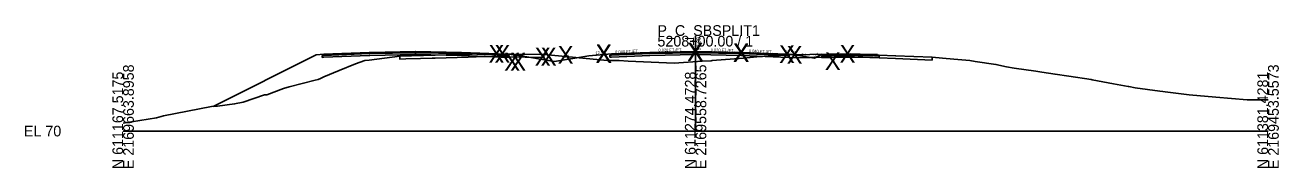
# Model space of a CAD drawing. Extents: x -26 to 1303, y -3010 to 12023.
# Drawn here: x 974.3 to 1302.8, y 5990.3 to 6027.8 of the extents above; entities that cross this region are included whole.
import ezdxf

# ---------------------------------------------------------------- set-up
doc = ezdxf.new("R2010")
doc.units = 0
for name, color, linetype in [('RD_GPK_XS_Cell', 7, 'Continuous'), ('RD_GPK_XS_Text_Node', 7, 'Continuous'), ('RD_XS_Base', 7, 'Continuous'), ('RD_XS_ExGround', 7, 'Continuous'), ('RD_XS_ExPaveRet', 7, 'Continuous'), ('RD_XS_Greenside', 7, 'Continuous'), ('RD_XS_Pave', 7, 'Continuous'), ('RD_XS_PaveOvlay_CP', 7, 'Continuous'), ('RD_XS_TieSlope', 7, 'Continuous'), ('RD_XS_TX_Elev_EX', 7, 'Continuous'), ('RD_XS_TX_Elev_PR', 7, 'Continuous'), ('RD_XS_TX_ShdSlope', 7, 'Continuous'), ('RD_XS_TX_Slope', 7, 'Continuous')]:
    doc.layers.add(name, color=color, linetype=linetype)

msp = doc.modelspace()

# ---------------------------------------------------------------- linework, layer by layer
at = {"layer": 'RD_GPK_XS_Cell'}
for p, q in [((1150, 6000), (1150, 6025)), ((1000, 6000), (1150, 6000)), ((1150, 6000), (1300, 6000))]:
    msp.add_line(p, q, dxfattribs=at)
at = {"layer": 'RD_XS_Base'}
for p, q in [((1052.12, 6019.84), (1052.61, 6019.86)), ((1052.12, 6019.83), (1052.12, 6019.84)), ((1052.12, 6019.34), (1052.12, 6019.83)), ((1052.61, 6019.36), (1052.12, 6019.34)), ((1052.61, 6019.86), (1052.62, 6019.86)), ((1052.62, 6019.36), (1052.61, 6019.36)), ((1052.62, 6019.86), (1064.47, 6020.33)), ((1064.47, 6019.83), (1052.62, 6019.36)), ((1064.47, 6020.33), (1064.62, 6020.34)), ((1064.62, 6019.84), (1064.47, 6019.83)), ((1064.62, 6020.34), (1076.6, 6020.58)), ((1076.6, 6020.08), (1064.62, 6019.84)), ((1076.6, 6020.58), (1076.62, 6020.58)), ((1076.62, 6020.08), (1076.6, 6020.08)), ((1076.62, 6020.58), (1076.62, 6020.74)), ((1076.62, 6020.74), (1076.62, 6020.74)), ((1076.62, 6020.74), (1076.62, 6020.74)), ((1076.62, 6020.74), (1076.62, 6020.08)), ((1076.62, 6020.58), (1076.62, 6020.74)), ((1076.62, 6020.74), (1076.62, 6020.08)), ((1076.62, 6020.58), (1076.62, 6020.58)), ((1076.62, 6020.58), (1076.62, 6020.08)), ((1076.65, 6020.58), (1076.62, 6020.58)), ((1076.62, 6020.58), (1076.62, 6020.08)), ((1088.62, 6020.34), (1076.62, 6020.58)), ((1076.62, 6020.58), (1076.62, 6020.58)), ((1076.62, 6020.08), (1076.65, 6020.08)), ((1076.62, 6020.08), (1076.62, 6020.08)), ((1076.62, 6020.08), (1076.62, 6020.08)), ((1076.62, 6020.08), (1088.62, 6019.84)), ((1100.62, 6019.86), (1088.62, 6020.34)), ((1088.62, 6019.84), (1101.12, 6019.34)), ((1090.62, 6020.26), (1090.62, 6020.26)), ((1090.62, 6019.76), (1090.62, 6019.76)), ((1101.12, 6019.84), (1100.62, 6019.86)), ((1100.62, 6019.86), (1100.62, 6019.86)), ((1101.12, 6019.34), (1101.12, 6019.84)), ((1101.12, 6019.84), (1101.12, 6019.84)), ((1101.12, 6019.34), (1101.12, 6019.34)), ((1101.12, 6019.34), (1101.12, 6019.34)), ((1127.5, 6019.92), (1128, 6019.94)), ((1127.5, 6019.42), (1127.5, 6019.92)), ((1127.5, 6019.92), (1127.5, 6019.92)), ((1128, 6019.44), (1127.5, 6019.42)), ((1127.5, 6019.42), (1127.5, 6019.42)), ((1127.5, 6019.42), (1127.5, 6019.42)), ((1128, 6019.94), (1138, 6020.34)), ((1128, 6019.94), (1128, 6019.94)), ((1138, 6019.84), (1128, 6019.44)), ((1128, 6019.44), (1128, 6019.44)), ((1136, 6020.26), (1136, 6020.26)), ((1136, 6019.76), (1136, 6019.76)), ((1138, 6020.34), (1150, 6020.58)), ((1150, 6020.08), (1138, 6019.84)), ((1150, 6020.58), (1150, 6020.74)), ((1150, 6020.74), (1150, 6020.08)), ((1150, 6020.58), (1150, 6020.08)), ((1150, 6020.58), (1150, 6020.58)), ((1162, 6020.34), (1150, 6020.58)), ((1150, 6020.58), (1150, 6020.58)), ((1150, 6020.08), (1150, 6020.08)), ((1150, 6020.08), (1150, 6020.08)), ((1150, 6020.08), (1162, 6019.84)), ((1173.93, 6019.86), (1162, 6020.34)), ((1162, 6020.34), (1162, 6020.34)), ((1162, 6019.84), (1162, 6019.84)), ((1162, 6019.84), (1174.43, 6019.34)), ((1174.43, 6019.84), (1173.93, 6019.86)), ((1173.93, 6019.86), (1173.93, 6019.86)), ((1174.43, 6019.34), (1174.43, 6019.84)), ((1174.43, 6019.84), (1174.43, 6019.84)), ((1174.43, 6019.34), (1174.43, 6019.34)), ((1174.43, 6019.34), (1174.43, 6019.34)), ((1183.11, 6019.77), (1183.61, 6019.78)), ((1183.11, 6019.27), (1183.11, 6019.77)), ((1183.61, 6019.28), (1183.11, 6019.27)), ((1183.61, 6019.78), (1185.61, 6019.82)), ((1185.61, 6019.32), (1183.61, 6019.28)), ((1185.61, 6019.82), (1190.61, 6019.92)), ((1190.61, 6019.42), (1185.61, 6019.32)), ((1190.61, 6019.98), (1190.61, 6020.08)), ((1190.61, 6020.08), (1190.61, 6019.82)), ((1190.61, 6019.92), (1190.61, 6019.98)), ((1192.56, 6019.88), (1190.61, 6019.92)), ((1190.61, 6019.92), (1190.61, 6019.42)), ((1190.61, 6019.82), (1190.61, 6019.42)), ((1190.61, 6019.42), (1192.56, 6019.38)), ((1195.62, 6019.82), (1192.56, 6019.88)), ((1192.56, 6019.38), (1195.62, 6019.32)), ((1196.87, 6019.79), (1195.62, 6019.82)), ((1195.62, 6019.32), (1196.56, 6019.3)), ((1196.56, 6019.3), (1198.12, 6019.27)), ((1197.62, 6019.78), (1196.87, 6019.79)), ((1197.8, 6019.77), (1197.62, 6019.78)), ((1198.12, 6019.77), (1197.8, 6019.77)), ((1198.12, 6019.45), (1198.12, 6019.77)), ((1198.12, 6019.27), (1198.12, 6019.45))]:
    msp.add_line(p, q, dxfattribs=at)
at = {"layer": 'RD_XS_ExGround'}
msp.add_lwpolyline([(1000, 6002.05), (1008.76, 6003.47), (1010.61, 6003.99), (1023.16, 6006.48), (1024.75, 6006.52), (1029.19, 6007.11), (1031.43, 6007.56), (1034.26, 6008.56), (1037.02, 6009.51), (1037.62, 6009.51), (1042.06, 6011.15), (1043.48, 6011.61), (1050.29, 6013.32), (1051.09, 6013.52), (1051.71, 6013.76), (1052.57, 6014.26), (1056.63, 6015.9), (1060.85, 6017.65), (1062.12, 6018.06), (1063.37, 6018.49), (1064.43, 6018.64), (1072.46, 6019.66), (1081.72, 6019.93), (1094.66, 6020.31), (1110.16, 6020.09), (1110.21, 6020.09), (1110.26, 6020.09), (1110.42, 6020.07), (1126.8, 6018.57), (1129.12, 6018.5), (1129.97, 6018.5), (1132.31, 6018.38), (1144.37, 6017.87), (1151.74, 6018.35), (1154.09, 6018.46), (1154.32, 6018.49), (1162.53, 6019.13), (1166.07, 6019.51), (1173.35, 6019.94), (1174.49, 6019.99), (1179.96, 6020.1), (1189.56, 6020.3), (1202.39, 6019.77), (1211.98, 6019.38), (1214.65, 6019.12), (1217.69, 6018.87), (1221.81, 6018.5), (1223.27, 6018.29), (1228.69, 6017.5), (1231.5, 6016.88), (1233.46, 6016.52), (1239.13, 6015.73), (1240.7, 6015.5), (1244.19, 6014.91), (1247.8, 6014.4), (1253.63, 6013.5), (1253.89, 6013.49), (1259.47, 6012.42), (1263.37, 6011.73), (1263.48, 6011.7), (1265.19, 6011.38), (1271.64, 6010.5), (1272.38, 6010.4), (1273.06, 6010.33), (1279.31, 6009.49), (1286.35, 6008.91), (1294.5, 6008.17), (1300, 6008.18)], dxfattribs=at)
at = {"layer": 'RD_XS_ExPaveRet'}
for points in [[(1074.06, 6019.71), (1072.46, 6019.66), (1072.46, 6019.1), (1072.46, 6018.91), (1074.06, 6018.96), (1077.91, 6019.07), (1080.94, 6019.16), (1081.72, 6019.18), (1090.37, 6019.43), (1094.66, 6019.56), (1100.53, 6019.48), (1110.16, 6019.34), (1110.21, 6019.34), (1110.21, 6019.34), (1110.21, 6019.34), (1110.21, 6019.34), (1110.21, 6019.34), (1110.21, 6020), (1110.21, 6020.09), (1110.21, 6020.09), (1110.21, 6020.09), (1110.21, 6020.09), (1110.21, 6020.09), (1110.16, 6020.09), (1100.53, 6020.23), (1094.66, 6020.31), (1090.37, 6020.18), (1081.72, 6019.93), (1080.94, 6019.91), (1077.91, 6019.82), (1074.06, 6019.71)], [(1074.06, 6019.71), (1072.46, 6019.66), (1072.46, 6019.1), (1072.46, 6018.91), (1074.06, 6018.96), (1077.91, 6019.07), (1080.94, 6019.16), (1081.72, 6019.18), (1090.37, 6019.43), (1094.66, 6019.56), (1100.53, 6019.48), (1110.16, 6019.34), (1110.21, 6019.34), (1110.21, 6019.34), (1110.21, 6019.34), (1110.21, 6019.34), (1110.21, 6020), (1110.21, 6020.09), (1110.21, 6020.09), (1110.21, 6020.09), (1110.21, 6020.09), (1110.16, 6020.09), (1100.53, 6020.23), (1094.66, 6020.31), (1090.37, 6020.18), (1081.72, 6019.93), (1080.94, 6019.91), (1077.91, 6019.82), (1074.06, 6019.71)], [(1211.98, 6019.38), (1202.39, 6019.77), (1202.39, 6019.77), (1189.56, 6020.3), (1189.56, 6020.3), (1179.96, 6020.1), (1179.96, 6020.1), (1174.49, 6019.99), (1174.49, 6019.99), (1174.49, 6019.24), (1174.49, 6019.24), (1174.49, 6019.24), (1179.96, 6019.35), (1179.96, 6019.35), (1189.56, 6019.55), (1189.56, 6019.55), (1202.39, 6019.02), (1202.39, 6019.02), (1211.98, 6018.63), (1211.98, 6018.63), (1211.98, 6018.63), (1211.98, 6019.38), (1211.98, 6019.38)], [(1211.98, 6019.38), (1202.39, 6019.77), (1189.56, 6020.3), (1179.96, 6020.1), (1174.49, 6019.99), (1174.49, 6019.99), (1174.49, 6019.24), (1174.49, 6019.24), (1179.96, 6019.35), (1189.56, 6019.55), (1202.39, 6019.02), (1211.98, 6018.63), (1211.98, 6019.38)]]:
    msp.add_lwpolyline(points, dxfattribs=at)
at = {"layer": 'RD_XS_Greenside'}
for p, q in [((1050.62, 6020.02), (1023.55, 6006.49)), ((1102.62, 6020.02), (1113.03, 6018.28)), ((1122, 6019.78), (1113.03, 6018.28)), ((1175.93, 6020.02), (1181.13, 6019.15)), ((1181.13, 6019.15), (1183.16, 6020.17))]:
    msp.add_line(p, q, dxfattribs=at)
at = {"layer": 'RD_XS_Pave'}
for p, q in [((1064.47, 6020.65), (1052.62, 6020.18)), ((1064.47, 6020.49), (1052.62, 6020.02)), ((1052.62, 6020.02), (1064.47, 6020.49)), ((1052.62, 6019.86), (1064.47, 6020.33)), ((1052.62, 6020.18), (1052.62, 6020.17)), ((1052.62, 6020.17), (1052.62, 6020.02)), ((1052.62, 6020.02), (1052.62, 6020.02)), ((1052.62, 6020.02), (1052.62, 6019.86)), ((1064.62, 6020.66), (1064.47, 6020.65)), ((1064.62, 6020.5), (1064.47, 6020.49)), ((1064.47, 6020.49), (1064.62, 6020.5)), ((1064.47, 6020.33), (1064.62, 6020.34)), ((1076.6, 6020.9), (1064.62, 6020.66)), ((1076.6, 6020.74), (1064.62, 6020.5)), ((1064.62, 6020.5), (1076.6, 6020.74)), ((1064.62, 6020.34), (1076.6, 6020.58)), ((1076.62, 6020.9), (1076.6, 6020.9)), ((1076.62, 6020.74), (1076.6, 6020.74)), ((1076.6, 6020.74), (1076.62, 6020.74)), ((1076.6, 6020.58), (1076.62, 6020.58)), ((1076.65, 6020.9), (1076.62, 6020.9)), ((1088.62, 6020.66), (1076.62, 6020.9)), ((1076.62, 6020.58), (1076.62, 6020.74)), ((1076.62, 6020.74), (1076.62, 6020.74)), ((1076.62, 6020.74), (1076.65, 6020.74)), ((1076.65, 6020.74), (1076.62, 6020.74)), ((1076.62, 6020.74), (1076.62, 6020.74)), ((1076.62, 6020.74), (1076.62, 6020.58)), ((1076.62, 6020.58), (1076.62, 6020.74)), ((1076.62, 6020.74), (1088.62, 6020.5)), ((1088.62, 6020.5), (1076.62, 6020.74)), ((1076.62, 6020.74), (1076.62, 6020.58)), ((1076.62, 6020.58), (1076.65, 6020.58)), ((1076.62, 6020.58), (1076.62, 6020.58)), ((1076.62, 6020.58), (1076.62, 6020.58)), ((1076.62, 6020.58), (1088.62, 6020.34)), ((1100.62, 6020.18), (1088.62, 6020.66)), ((1088.62, 6020.5), (1100.62, 6020.02)), ((1100.62, 6020.02), (1088.62, 6020.5)), ((1088.62, 6020.34), (1100.62, 6019.86)), ((1090.62, 6020.58), (1090.62, 6020.58)), ((1090.62, 6020.42), (1090.62, 6020.42)), ((1090.62, 6020.42), (1090.62, 6020.42)), ((1090.62, 6020.26), (1090.62, 6020.26)), ((1100.62, 6020.02), (1100.62, 6020.18)), ((1100.62, 6020.18), (1100.62, 6020.18)), ((1100.62, 6020.02), (1100.62, 6020.02)), ((1100.62, 6020.02), (1100.62, 6020.02)), ((1100.62, 6019.86), (1100.62, 6020.02)), ((1100.62, 6020.02), (1100.62, 6020.02)), ((1100.62, 6019.86), (1100.62, 6019.86)), ((1100.62, 6019.86), (1100.62, 6019.86)), ((1138, 6020.66), (1128, 6020.26)), ((1138, 6020.5), (1128, 6020.1)), ((1128, 6020.1), (1138, 6020.5)), ((1128, 6019.94), (1138, 6020.34)), ((1128, 6020.26), (1128, 6020.26)), ((1128, 6020.26), (1128, 6020.1)), ((1128, 6020.1), (1128, 6020.1)), ((1128, 6020.1), (1128, 6019.94)), ((1128, 6020.1), (1128, 6020.1)), ((1128, 6020.1), (1128, 6020.1)), ((1128, 6019.94), (1128, 6019.94)), ((1128, 6019.94), (1128, 6019.94)), ((1136, 6020.58), (1136, 6020.58)), ((1136, 6020.42), (1136, 6020.42)), ((1136, 6020.42), (1136, 6020.42)), ((1136, 6020.26), (1136, 6020.26)), ((1150, 6020.9), (1138, 6020.66)), ((1150, 6020.74), (1138, 6020.5)), ((1138, 6020.5), (1150, 6020.74)), ((1138, 6020.34), (1150, 6020.58)), ((1162, 6020.66), (1150, 6020.9)), ((1150, 6020.58), (1150, 6020.74)), ((1150, 6020.74), (1162, 6020.5)), ((1162, 6020.5), (1150, 6020.74)), ((1150, 6020.74), (1150, 6020.74)), ((1150, 6020.74), (1150, 6020.58)), ((1150, 6020.58), (1150, 6020.58)), ((1150, 6020.58), (1150, 6020.58)), ((1150, 6020.58), (1150, 6020.58)), ((1150, 6020.58), (1162, 6020.34)), ((1173.93, 6020.18), (1162, 6020.66)), ((1162, 6020.66), (1162, 6020.66)), ((1162, 6020.5), (1162, 6020.5)), ((1162, 6020.5), (1173.93, 6020.02)), ((1173.93, 6020.02), (1162, 6020.5)), ((1162, 6020.5), (1162, 6020.5)), ((1162, 6020.34), (1162, 6020.34)), ((1162, 6020.34), (1173.93, 6019.86)), ((1173.93, 6020.02), (1173.93, 6020.18)), ((1173.93, 6020.18), (1173.93, 6020.18)), ((1173.93, 6020.02), (1173.93, 6020.02)), ((1173.93, 6020.02), (1173.93, 6020.02)), ((1173.93, 6019.86), (1173.93, 6020.02)), ((1173.93, 6020.02), (1173.93, 6020.02)), ((1173.93, 6019.86), (1173.93, 6019.86)), ((1173.93, 6019.86), (1173.93, 6019.86)), ((1184.78, 6020.12), (1183.61, 6020.1)), ((1183.61, 6020.1), (1183.61, 6020.03)), ((1183.61, 6020.03), (1183.61, 6019.94)), ((1185.61, 6019.98), (1183.61, 6019.94)), ((1183.61, 6019.94), (1184.44, 6019.95)), ((1183.61, 6019.94), (1183.61, 6019.78)), ((1183.61, 6019.78), (1185.61, 6019.82)), ((1184.44, 6019.95), (1185.61, 6019.98)), ((1185.61, 6020.14), (1184.78, 6020.12)), ((1188.61, 6020.2), (1185.61, 6020.14)), ((1190.61, 6020.08), (1185.61, 6019.98)), ((1185.61, 6019.98), (1188.61, 6020.04)), ((1185.61, 6019.82), (1190.61, 6019.92)), ((1190.61, 6020.24), (1188.61, 6020.2)), ((1188.61, 6020.04), (1190.61, 6020.08)), ((1192.56, 6020.2), (1190.61, 6020.24)), ((1190.61, 6020.08), (1192.56, 6020.04)), ((1195.62, 6019.98), (1190.61, 6020.08)), ((1190.61, 6020.08), (1190.61, 6019.92)), ((1190.61, 6019.92), (1190.61, 6020.08)), ((1190.61, 6019.92), (1195.62, 6019.82)), ((1195.62, 6020.14), (1192.56, 6020.2)), ((1192.56, 6020.04), (1195.62, 6019.98)), ((1196.87, 6020.11), (1195.62, 6020.14)), ((1195.62, 6019.98), (1196.37, 6019.96)), ((1197.62, 6019.94), (1195.62, 6019.98)), ((1195.62, 6019.82), (1197.62, 6019.78)), ((1196.37, 6019.96), (1197.62, 6019.94)), ((1197.62, 6020.1), (1196.87, 6020.11)), ((1197.62, 6020), (1197.62, 6020.1)), ((1197.62, 6019.94), (1197.62, 6020)), ((1197.62, 6019.78), (1197.62, 6019.94))]:
    msp.add_line(p, q, dxfattribs=at)
at = {"layer": 'RD_XS_PaveOvlay_CP'}
for p, q in [((1052.62, 6020.18), (1064.62, 6020.66)), ((1064.62, 6020.66), (1076.62, 6020.9)), ((1076.62, 6020.9), (1088.62, 6020.66)), ((1088.62, 6020.66), (1100.62, 6020.18)), ((1138, 6020.66), (1128, 6020.26)), ((1128, 6020.26), (1128, 6020.26)), ((1136, 6020.58), (1136, 6020.58)), ((1150, 6020.9), (1138, 6020.66)), ((1162, 6020.66), (1150, 6020.9)), ((1173.93, 6020.18), (1162, 6020.66)), ((1162, 6020.66), (1162, 6020.66)), ((1173.93, 6020.18), (1173.93, 6020.18)), ((1183.61, 6020.1), (1185.61, 6020.14)), ((1185.61, 6020.14), (1190.61, 6020.24)), ((1190.61, 6020.24), (1195.62, 6020.14)), ((1195.62, 6020.14), (1197.62, 6020.1))]:
    msp.add_line(p, q, dxfattribs=at)
at = {"layer": 'RD_XS_TieSlope'}
for p, q in [((1052.62, 6020.18), (1050.62, 6020.02)), ((1100.62, 6020.18), (1102.62, 6020.02)), ((1128, 6020.26), (1122, 6019.78)), ((1173.93, 6020.18), (1175.93, 6020.02))]:
    msp.add_line(p, q, dxfattribs=at)

# ---------------------------------------------------------------- texts
at = {"layer": 'RD_GPK_XS_Cell'}
for s, p in [('P_C_SBSPLIT1', (1140, 6025)), ('5208+00.00 / 1', (1140, 6022.2)), ('EL 70', (974, 5998.6))]:
    msp.add_text(s, height=2.8, dxfattribs=at).set_placement(p)
for s, p in [('N 611167.5175', (1000, 5990)), ('E 2169663.8958', (1002.8, 5990)), ('N 611274.4728', (1150, 5990)), ('E 2169558.7265', (1152.8, 5990)), ('E 2169453.5573', (1302.8, 5990)), ('N 611381.4281', (1300, 5990))]:
    msp.add_text(s, height=2.8, rotation=90, dxfattribs=at).set_placement(p)
at = {"layer": 'RD_GPK_XS_Text_Node'}
for p in [(1095.72, 6017.92), (1097.28, 6017.92), (1113.84, 6017.67), (1123.84, 6018.07), (1123.84, 6017.91), (1147.84, 6018.55), (1147.84, 6018.39), (1159.84, 6018.31), (1159.84, 6018.15), (1171.84, 6017.83), (1173.84, 6017.67), (1187.71, 6017.94), (1099.84, 6015.86), (1101.4, 6015.86), (1107.84, 6017.19), (1109.4, 6017.2), (1183.84, 6016.01)]:
    msp.add_text('X', height=4.69, dxfattribs=at).set_placement(p)
at = {"layer": 'RD_XS_TX_Elev_EX'}
msp.add_text('88.24', height=0.6, rotation=90, dxfattribs=at).set_placement((1149.62, 6021.94))
at = {"layer": 'RD_XS_TX_Elev_PR'}
msp.add_text('90.90', height=1, rotation=90, dxfattribs=at).set_placement((1151.28, 6021.18))
at = {"layer": 'RD_XS_TX_ShdSlope'}
for rotation, p in [(4.5739, (1123.78, 6020.13)), (355.4261, (1173.45, 6020.5))]:
    msp.add_text('12.5:1', height=0.75, rotation=rotation, dxfattribs=at).set_placement(p)
at = {"layer": 'RD_XS_TX_Slope'}
for s, rotation, p in [('6:1', 9.4642, (1115.57, 6019.12)), ('0.040 FT./FT.', 2.2906, (1128.93, 6020.39)), ('0.020 FT./FT.', 1.1458, (1140.27, 6020.87)), ('0.020 FT./FT.', 358.8542, (1153.94, 6020.92)), ('0.040 FT./FT.', 357.7094, (1163.94, 6020.68)), ('6:1', 350.5358, (1177.64, 6019.79)), ('2:1', 26.5651, (1181.16, 6019.36))]:
    msp.add_text(s, height=0.75, rotation=rotation, dxfattribs=at).set_placement(p)

doc.saveas('drawing.dxf')
